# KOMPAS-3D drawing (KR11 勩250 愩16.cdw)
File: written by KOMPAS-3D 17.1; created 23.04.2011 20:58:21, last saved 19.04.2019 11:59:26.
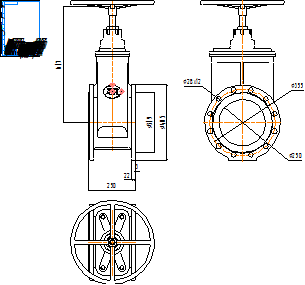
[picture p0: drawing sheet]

Sheet 1: A4, portrait

Title block, sheet 1: name: KR11 Ду250 Ру16; material: Внимание! Данный продукт является объектом авторского права ООО «Торговый Дом АДЛ». / Запрещается изменение, копирование, распространение / (в том числе путем копирования на другие сайты и ресурсы в Интернете) / или любое иное использование информации и объектов без предварительного / согласия правообладателя (ООО «Торговый Дом АДЛ»).; scale: 1:1; sheets: 1; organisation: ООО "Торговый дом АДЛ"; sheet format: A4; stored path: \\adlc.lan\data\АДЛ_ПКД\3D-модели\ADL production\Клиновые задвижки серии KR ГРАНАР\Клиновые задвижки KR11\KOMPAS 2D\KR11 Ду250 Ру16.cdw

Views: Спереди 4, Проекционный вид 5
Dimensions and other numbers on the sheet: 250; 22; 3; 405; 319; 617; 1:1; 1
